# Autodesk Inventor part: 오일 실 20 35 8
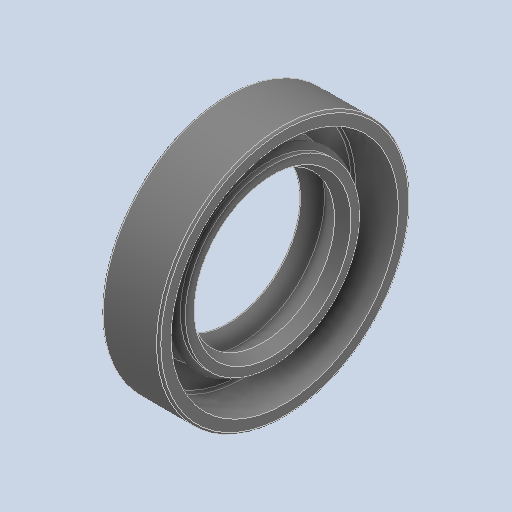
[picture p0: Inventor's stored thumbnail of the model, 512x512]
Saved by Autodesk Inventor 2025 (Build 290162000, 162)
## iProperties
Created: 2024-08
Part Number: 오일 실 20 35 8
Material: 고무
Description: 오일-실
Document SubType Name: Modeling
Designer: rese9
Density: 0.93 g/cm^3
Appearance: 기본값
Author: jhkim
Sending System: Autodesk Inventor 2025
Preprocessor: ST-DEVELOPER v20
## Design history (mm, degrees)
feature "Solid1"
node "솔리드1"
